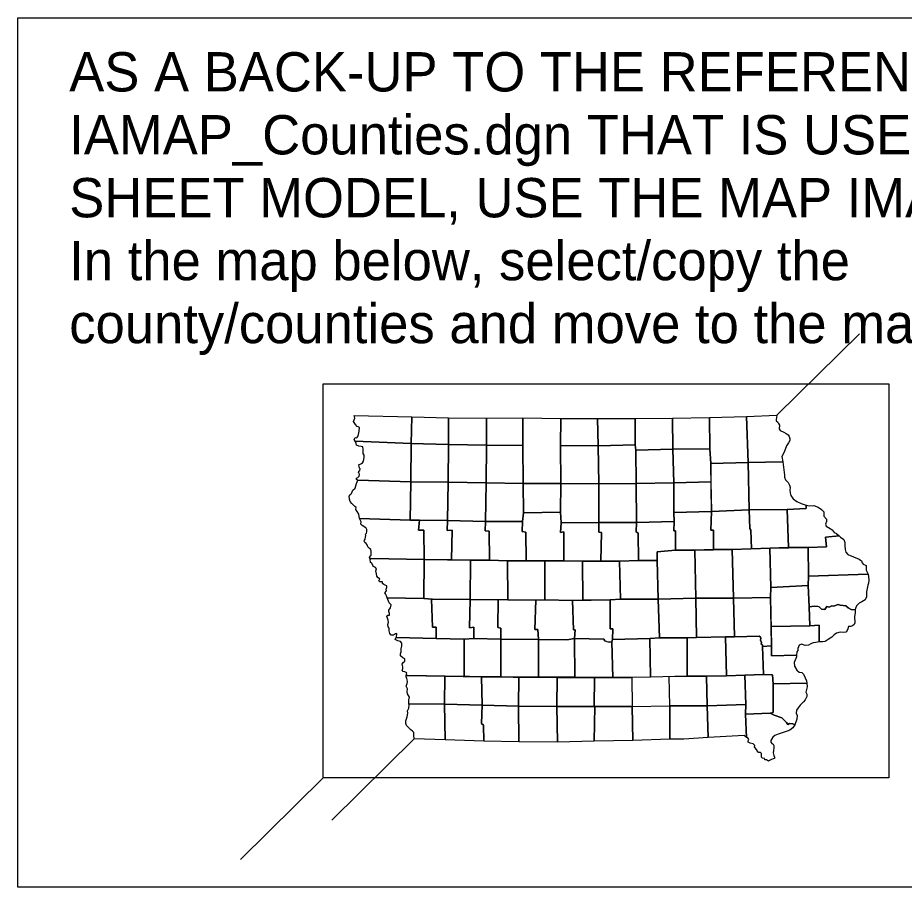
# Model space of a CAD drawing. Extents: x -0.84 to 4.97, y -1.01 to 2.42.
# Drawn here: x -0.1003 to 0.3692, y -0.6865 to -0.2258 of the extents above; entities that cross this region are included whole.
import ezdxf

# ---------------------------------------------------------------- set-up
doc = ezdxf.new("R2010")
doc.units = 0
doc.layers.add('tdCoTitleBlock', color=7, linetype='Continuous')
doc.layers.add('TextNonPlot', color=7, linetype='Continuous')

msp = doc.modelspace()

# ---------------------------------------------------------------- linework, layer by layer
at = {"layer": 'tdCoTitleBlock'}
for points in [[(0.07788, -0.43657), (0.10843, -0.43731), (0.10809, -0.45142), (0.07838, -0.45021), (0.07776, -0.44923), (0.07832, -0.44824), (0.07927, -0.44843), (0.07977, -0.44775), (0.08007, -0.44667), (0.08041, -0.44485), (0.08062, -0.44282), (0.07997, -0.44257), (0.07935, -0.44233), (0.07858, -0.44134), (0.07755, -0.43971), (0.0782, -0.43799)], [(0.28556, -0.43711), (0.30171, -0.43644), (0.30149, -0.4377), (0.30131, -0.43851), (0.30138, -0.43931), (0.30218, -0.44014), (0.30265, -0.44075), (0.30302, -0.44167), (0.3029, -0.44368), (0.30346, -0.44457), (0.30535, -0.44536), (0.30658, -0.44613), (0.3077, -0.44683), (0.30829, -0.44772), (0.30857, -0.44883), (0.30851, -0.44982), (0.30786, -0.45099), (0.30682, -0.45263), (0.30562, -0.45599), (0.3043, -0.45824), (0.30493, -0.46116), (0.28658, -0.46137)], [(0.10843, -0.43731), (0.12788, -0.43771), (0.12783, -0.452), (0.10809, -0.45142)], [(0.12788, -0.43771), (0.14789, -0.43796), (0.14784, -0.45219), (0.12783, -0.452)], [(0.14789, -0.43796), (0.16716, -0.43778), (0.16711, -0.45238), (0.14784, -0.45219)], [(0.16716, -0.43778), (0.1873, -0.43821), (0.18715, -0.45253), (0.18736, -0.47252), (0.16738, -0.47252), (0.16711, -0.45238)], [(0.1873, -0.43821), (0.20669, -0.43821), (0.20704, -0.45262), (0.18715, -0.45253)], [(0.20669, -0.43821), (0.2267, -0.43809), (0.22671, -0.45204), (0.20704, -0.45262)], [(0.2267, -0.43809), (0.24643, -0.4379), (0.24664, -0.45438), (0.227, -0.455), (0.22671, -0.45204)], [(0.24643, -0.4379), (0.26604, -0.4376), (0.26627, -0.4542), (0.24664, -0.45438)], [(0.26604, -0.4376), (0.28556, -0.43711), (0.28658, -0.46137), (0.2667, -0.46196), (0.26627, -0.4542)], [(0.07838, -0.45021), (0.10809, -0.45142), (0.10787, -0.47168), (0.07977, -0.47085), (0.07915, -0.47054), (0.07903, -0.46983), (0.07983, -0.46943), (0.08041, -0.46866), (0.08063, -0.46783), (0.08056, -0.46712), (0.08022, -0.46672), (0.08031, -0.46607), (0.08087, -0.46561), (0.08108, -0.46487), (0.08068, -0.46438), (0.08043, -0.46348), (0.08033, -0.46259), (0.08107, -0.4624), (0.08169, -0.462), (0.08221, -0.4616), (0.08274, -0.46083), (0.08292, -0.45978), (0.08319, -0.45855), (0.08319, -0.45759), (0.08266, -0.45661), (0.08254, -0.45531), (0.08269, -0.45448), (0.08241, -0.45322), (0.08157, -0.45298), (0.08027, -0.45277), (0.07916, -0.45225), (0.07891, -0.45145)], [(0.10809, -0.45142), (0.12783, -0.452), (0.12758, -0.47193), (0.10787, -0.47168)], [(0.12783, -0.452), (0.14784, -0.45219), (0.14777, -0.47215), (0.12758, -0.47193)], [(0.14784, -0.45219), (0.16711, -0.45238), (0.16738, -0.47252), (0.14777, -0.47215)], [(0.18715, -0.45253), (0.20704, -0.45262), (0.2075, -0.47267), (0.18736, -0.47252)], [(0.20704, -0.45262), (0.22671, -0.45204), (0.227, -0.455), (0.22723, -0.47258), (0.2075, -0.47267)], [(0.227, -0.455), (0.24664, -0.45438), (0.24706, -0.47218), (0.22723, -0.47258)], [(0.24664, -0.45438), (0.26627, -0.4542), (0.2667, -0.46196), (0.26682, -0.47175), (0.24706, -0.47218)], [(0.2667, -0.46196), (0.28658, -0.46137), (0.28712, -0.4866), (0.26714, -0.48743)], [(0.28658, -0.46137), (0.30493, -0.46116), (0.30553, -0.4668), (0.30581, -0.46815), (0.30572, -0.46929), (0.30631, -0.47055), (0.30764, -0.472), (0.30842, -0.47344), (0.3087, -0.47477), (0.30861, -0.47609), (0.30874, -0.47757), (0.30911, -0.47898), (0.31032, -0.48064), (0.31227, -0.48212), (0.31465, -0.48316), (0.31725, -0.48413), (0.31726, -0.48574), (0.30713, -0.48638), (0.28712, -0.4866)], [(0.07977, -0.47085), (0.10787, -0.47168), (0.10753, -0.49192), (0.08072, -0.49117), (0.08035, -0.48889), (0.07942, -0.48733), (0.0787, -0.4864), (0.07898, -0.4852), (0.0782, -0.48477), (0.07662, -0.48321), (0.07576, -0.48207), (0.07538, -0.48081), (0.07516, -0.4793), (0.07572, -0.4785), (0.07645, -0.47779), (0.07707, -0.47606), (0.07836, -0.47513), (0.07906, -0.47254)], [(0.10787, -0.47168), (0.12758, -0.47193), (0.12729, -0.4922), (0.11244, -0.49194), (0.10753, -0.49192)], [(0.12758, -0.47193), (0.14777, -0.47215), (0.14746, -0.49279), (0.12729, -0.4922)], [(0.14777, -0.47215), (0.16738, -0.47252), (0.16755, -0.48807), (0.16707, -0.49269), (0.14746, -0.49279)], [(0.16738, -0.47252), (0.18736, -0.47252), (0.18707, -0.48771), (0.16755, -0.48807)], [(0.18736, -0.47252), (0.2075, -0.47267), (0.20737, -0.49331), (0.18739, -0.49334), (0.18707, -0.48771)], [(0.2075, -0.47267), (0.22723, -0.47258), (0.22741, -0.49322), (0.20743, -0.49325)], [(0.22723, -0.47258), (0.24706, -0.47218), (0.24719, -0.48798), (0.24727, -0.4927), (0.22741, -0.49322)], [(0.24706, -0.47218), (0.26682, -0.47175), (0.26714, -0.48743), (0.24719, -0.48798)], [(0.16755, -0.48807), (0.18707, -0.48771), (0.18739, -0.49334), (0.18704, -0.49849), (0.18895, -0.49823), (0.18881, -0.51357), (0.1789, -0.5136), (0.16889, -0.51339), (0.16869, -0.49829), (0.16681, -0.49799), (0.16707, -0.49269)], [(0.24719, -0.48798), (0.26714, -0.48743), (0.2668, -0.49732), (0.26819, -0.49737), (0.26822, -0.50754), (0.25831, -0.50797), (0.24799, -0.50797), (0.24796, -0.49771), (0.24716, -0.49769), (0.24727, -0.4927)], [(0.26714, -0.48743), (0.28712, -0.4866), (0.28739, -0.49639), (0.28798, -0.49722), (0.2882, -0.50717), (0.27801, -0.50748), (0.26822, -0.50754), (0.26819, -0.49737), (0.2668, -0.49732)], [(0.28712, -0.4866), (0.30713, -0.48638), (0.3078, -0.50655), (0.2882, -0.50717), (0.28798, -0.49722), (0.28739, -0.49639)], [(0.30713, -0.48638), (0.31726, -0.48574), (0.31725, -0.48413), (0.31892, -0.48438), (0.32127, -0.48431), (0.32365, -0.48507), (0.32526, -0.48636), (0.32653, -0.48765), (0.3265, -0.48987), (0.32808, -0.49155), (0.32796, -0.49276), (0.32747, -0.49411), (0.32775, -0.49525), (0.33001, -0.49642), (0.331, -0.49715), (0.33205, -0.4985), (0.33326, -0.49912), (0.33462, -0.50028), (0.32746, -0.50095), (0.32794, -0.50619), (0.31824, -0.5064), (0.3078, -0.50655)], [(0.08072, -0.49117), (0.10753, -0.49192), (0.11244, -0.49194), (0.11184, -0.49733), (0.1148, -0.49729), (0.11485, -0.51275), (0.0868, -0.51234), (0.08628, -0.51272), (0.08591, -0.51173), (0.08655, -0.51093), (0.08686, -0.51053), (0.0868, -0.50979), (0.08676, -0.50889), (0.08692, -0.50837), (0.0867, -0.50748), (0.08589, -0.50693), (0.08506, -0.50616), (0.08475, -0.50499), (0.08416, -0.50434), (0.08348, -0.50388), (0.08307, -0.50315), (0.08329, -0.50256), (0.08359, -0.50207), (0.08378, -0.50108), (0.08396, -0.50016), (0.0839, -0.49945), (0.08433, -0.49883), (0.08451, -0.49818), (0.08451, -0.49695), (0.08426, -0.49615), (0.0837, -0.49584), (0.0829, -0.49539), (0.08215, -0.49477), (0.08135, -0.49403), (0.08153, -0.4928)], [(0.11244, -0.49194), (0.12729, -0.4922), (0.12709, -0.49744), (0.12981, -0.49737), (0.12939, -0.51301), (0.11485, -0.51275), (0.1148, -0.49729), (0.11184, -0.49733)], [(0.12729, -0.4922), (0.14746, -0.49279), (0.14717, -0.49765), (0.14939, -0.49777), (0.1495, -0.51314), (0.13946, -0.51323), (0.12939, -0.51301), (0.12981, -0.49737), (0.12709, -0.49744)], [(0.14746, -0.49279), (0.16707, -0.49269), (0.16681, -0.49799), (0.16869, -0.49829), (0.16889, -0.51339), (0.15901, -0.51363), (0.1495, -0.51314), (0.14939, -0.49777), (0.14717, -0.49765)], [(0.22741, -0.49322), (0.24727, -0.4927), (0.24716, -0.49769), (0.24796, -0.49771), (0.24799, -0.50797), (0.23839, -0.50871), (0.23834, -0.51342), (0.22837, -0.51342), (0.22823, -0.49894), (0.22727, -0.49824)], [(0.18739, -0.49334), (0.20743, -0.49325), (0.20739, -0.49836), (0.20884, -0.49854), (0.20854, -0.51367), (0.19869, -0.51379), (0.18881, -0.51357), (0.18895, -0.49823), (0.18704, -0.49849)], [(0.20743, -0.49325), (0.22741, -0.49322), (0.22727, -0.49824), (0.22823, -0.49894), (0.22837, -0.51342), (0.21842, -0.51367), (0.20854, -0.51367), (0.20884, -0.49854), (0.20739, -0.49836)], [(0.31824, -0.5064), (0.32794, -0.50619), (0.32746, -0.50095), (0.33462, -0.50028), (0.33546, -0.50102), (0.33725, -0.50228), (0.33772, -0.50378), (0.33769, -0.50557), (0.33791, -0.50748), (0.33832, -0.50902), (0.33934, -0.51025), (0.34531, -0.51263), (0.34645, -0.51349), (0.34683, -0.51463), (0.34739, -0.51534), (0.34896, -0.51601), (0.34903, -0.51856), (0.35006, -0.52062), (0.3185, -0.52171)], [(0.27801, -0.50748), (0.29805, -0.50689), (0.29857, -0.52765), (0.29837, -0.53295), (0.27876, -0.53338)], [(0.29805, -0.50689), (0.31824, -0.5064), (0.3185, -0.52171), (0.31836, -0.52664), (0.29857, -0.52765)], [(0.23839, -0.50871), (0.24799, -0.50797), (0.25831, -0.50797), (0.25884, -0.53335), (0.23877, -0.53378), (0.23834, -0.51342)], [(0.25831, -0.50797), (0.27801, -0.50748), (0.27876, -0.53338), (0.25884, -0.53335)], [(0.08628, -0.51272), (0.0868, -0.51234), (0.11485, -0.51275), (0.11466, -0.53357), (0.09536, -0.53314), (0.09492, -0.53209), (0.09452, -0.53108), (0.09402, -0.53046), (0.09488, -0.52941), (0.09476, -0.52864), (0.09506, -0.52769), (0.09506, -0.52679), (0.09432, -0.52637), (0.09432, -0.52637), (0.09348, -0.52609), (0.09293, -0.52548), (0.09289, -0.52471), (0.09206, -0.52465), (0.09144, -0.52465), (0.09098, -0.5241), (0.09144, -0.52311), (0.09063, -0.52247), (0.08989, -0.5217), (0.08964, -0.52047), (0.08939, -0.51884), (0.08966, -0.51782), (0.08966, -0.51782), (0.0892, -0.51705), (0.08811, -0.51662), (0.08768, -0.51607), (0.08727, -0.51481), (0.08653, -0.51438)], [(0.11485, -0.51275), (0.13946, -0.51323), (0.1393, -0.53405), (0.11935, -0.53377), (0.11466, -0.53357)], [(0.13946, -0.51323), (0.1495, -0.51314), (0.15901, -0.51363), (0.15916, -0.53418), (0.1393, -0.53405)], [(0.15901, -0.51363), (0.1789, -0.5136), (0.17886, -0.53427), (0.17404, -0.53441), (0.15916, -0.53418)], [(0.1789, -0.5136), (0.19869, -0.51379), (0.199, -0.53442), (0.19353, -0.53447), (0.17886, -0.53427)], [(0.19869, -0.51379), (0.21842, -0.51367), (0.21894, -0.53381), (0.21345, -0.53426), (0.199, -0.53442)], [(0.21842, -0.51367), (0.22837, -0.51342), (0.23834, -0.51342), (0.23877, -0.53378), (0.21894, -0.53381)], [(0.3185, -0.52171), (0.35006, -0.52062), (0.35025, -0.52179), (0.35037, -0.52373), (0.35026, -0.52531), (0.34995, -0.52635), (0.34952, -0.5282), (0.34919, -0.52999), (0.3491, -0.53264), (0.34846, -0.53424), (0.34673, -0.53526), (0.34538, -0.53601), (0.34393, -0.53743), (0.34338, -0.53879), (0.34322, -0.53946), (0.341, -0.53932), (0.33952, -0.53852), (0.33822, -0.53732), (0.33676, -0.53724), (0.33519, -0.53709), (0.3342, -0.53675), (0.33173, -0.5375), (0.33077, -0.53735), (0.32942, -0.53815), (0.32892, -0.53788), (0.32812, -0.53766), (0.3272, -0.53936), (0.32531, -0.53918), (0.3242, -0.53789), (0.32169, -0.53753), (0.31876, -0.53785), (0.31836, -0.52664)], [(0.29857, -0.52765), (0.31836, -0.52664), (0.31876, -0.53785), (0.31913, -0.54789), (0.29863, -0.54829), (0.29837, -0.53295)], [(0.09536, -0.53314), (0.11466, -0.53357), (0.11878, -0.53377), (0.11924, -0.54865), (0.12134, -0.54877), (0.12131, -0.55469), (0.10019, -0.55413), (0.10035, -0.55204), (0.09967, -0.55219), (0.09875, -0.5529), (0.09742, -0.55288), (0.09677, -0.55205), (0.09639, -0.55069), (0.09645, -0.54921), (0.09589, -0.54845), (0.09574, -0.54731), (0.09601, -0.5461), (0.09579, -0.54496), (0.09548, -0.54392), (0.09511, -0.543), (0.09563, -0.54238), (0.09656, -0.54238), (0.09652, -0.54139), (0.09618, -0.54047), (0.09621, -0.53973), (0.09716, -0.53852), (0.0974, -0.53692), (0.09644, -0.53582)], [(0.11878, -0.53377), (0.1393, -0.53405), (0.13894, -0.54902), (0.14117, -0.54871), (0.14127, -0.55471), (0.13603, -0.55504), (0.12131, -0.55469), (0.12134, -0.54877), (0.11924, -0.54865)], [(0.1393, -0.53405), (0.15416, -0.53404), (0.15386, -0.54882), (0.15543, -0.54919), (0.15551, -0.55498), (0.14127, -0.55471), (0.14117, -0.54871), (0.13894, -0.54902)], [(0.15416, -0.53404), (0.15916, -0.53418), (0.17404, -0.53441), (0.17353, -0.5499), (0.17514, -0.54999), (0.17549, -0.55525), (0.15551, -0.55498), (0.15543, -0.54919), (0.15386, -0.54882)], [(0.17404, -0.53441), (0.17886, -0.53427), (0.19353, -0.53447), (0.19404, -0.55002), (0.19496, -0.55014), (0.19461, -0.55477), (0.19041, -0.55539), (0.17549, -0.55525), (0.17514, -0.54999), (0.17353, -0.5499)], [(0.19404, -0.55002), (0.19353, -0.53447), (0.21345, -0.53426), (0.21337, -0.5495), (0.21476, -0.54965), (0.21468, -0.55523), (0.21431, -0.55652), (0.21295, -0.55668), (0.21178, -0.5565), (0.21064, -0.55586), (0.21002, -0.55512), (0.19461, -0.55477), (0.19496, -0.55014)], [(0.21345, -0.53426), (0.21894, -0.53381), (0.23877, -0.53378), (0.23957, -0.55438), (0.23444, -0.55474), (0.21468, -0.55523), (0.21476, -0.54965), (0.21337, -0.5495)], [(0.23877, -0.53378), (0.25884, -0.53335), (0.25918, -0.5542), (0.23957, -0.55438)], [(0.25884, -0.53335), (0.27876, -0.53338), (0.27931, -0.55389), (0.27459, -0.55378), (0.25918, -0.5542)], [(0.27876, -0.53338), (0.29837, -0.53295), (0.2989, -0.55851), (0.29405, -0.5589), (0.29408, -0.55806), (0.2934, -0.5577), (0.29352, -0.55683), (0.29303, -0.55557), (0.29327, -0.55449), (0.29299, -0.554), (0.29228, -0.55348), (0.27931, -0.55389)], [(0.31876, -0.53785), (0.32169, -0.53753), (0.3233, -0.53762), (0.3242, -0.53789), (0.32531, -0.53918), (0.3272, -0.53936), (0.32812, -0.53766), (0.32892, -0.53788), (0.32942, -0.53815), (0.33077, -0.53735), (0.33173, -0.5375), (0.3342, -0.53675), (0.33519, -0.53709), (0.33676, -0.53724), (0.33822, -0.53732), (0.33952, -0.53852), (0.341, -0.53932), (0.34322, -0.53946), (0.34311, -0.54113), (0.34283, -0.5431), (0.34297, -0.54633), (0.34272, -0.54735), (0.34173, -0.54797), (0.34093, -0.54828), (0.34022, -0.54828), (0.33973, -0.54841), (0.33933, -0.54952), (0.33902, -0.55044), (0.33822, -0.55125), (0.33693, -0.55143), (0.33532, -0.55132), (0.33322, -0.55194), (0.33199, -0.55277), (0.33079, -0.55404), (0.32891, -0.55522), (0.32728, -0.55627), (0.32579, -0.55652), (0.32419, -0.55646), (0.32419, -0.54762), (0.31913, -0.54789)], [(0.29863, -0.54829), (0.31913, -0.54789), (0.32419, -0.54762), (0.32419, -0.55646), (0.32243, -0.55681), (0.32098, -0.55706), (0.31974, -0.55752), (0.31848, -0.55814), (0.31678, -0.5584), (0.31474, -0.55769), (0.3136, -0.55816), (0.31289, -0.55998), (0.31287, -0.56103), (0.31228, -0.56177), (0.31219, -0.56349), (0.29892, -0.5639), (0.2989, -0.55851)], [(0.25417, -0.55434), (0.25918, -0.5542), (0.27459, -0.55378), (0.27498, -0.57439), (0.26452, -0.57463), (0.25429, -0.57463)], [(0.27459, -0.55378), (0.27931, -0.55389), (0.29228, -0.55348), (0.29299, -0.554), (0.29327, -0.55449), (0.29303, -0.55557), (0.29334, -0.55625), (0.29352, -0.55683), (0.2934, -0.5577), (0.29408, -0.55806), (0.29405, -0.5589), (0.29459, -0.5738), (0.28483, -0.57405), (0.27498, -0.57439)], [(0.10019, -0.55413), (0.12131, -0.55469), (0.13603, -0.55504), (0.13611, -0.57478), (0.10603, -0.57422), (0.10535, -0.57429), (0.10581, -0.57287), (0.10464, -0.57238), (0.10371, -0.57217), (0.10331, -0.57149), (0.10365, -0.57069), (0.10361, -0.56961), (0.1033, -0.56823), (0.10373, -0.56739), (0.10475, -0.56671), (0.10474, -0.56554), (0.1036, -0.56487), (0.10236, -0.56395), (0.10233, -0.56278), (0.10275, -0.56167), (0.10275, -0.5601), (0.10309, -0.55862), (0.10314, -0.55711), (0.10246, -0.55622), (0.10098, -0.55594), (0.09953, -0.55518), (0.09989, -0.55432)], [(0.13603, -0.55504), (0.14127, -0.55471), (0.15551, -0.55498), (0.15553, -0.57506), (0.14939, -0.57495), (0.13898, -0.57486), (0.13611, -0.57478)], [(0.15551, -0.55498), (0.17549, -0.55525), (0.17539, -0.57518), (0.16208, -0.57516), (0.15553, -0.57506)], [(0.17549, -0.55525), (0.19041, -0.55539), (0.19461, -0.55477), (0.19473, -0.57519), (0.17539, -0.57518)], [(0.19461, -0.55477), (0.21002, -0.55512), (0.21064, -0.55586), (0.21295, -0.55668), (0.21431, -0.55652), (0.21489, -0.57534), (0.19473, -0.57519)], [(0.21468, -0.55523), (0.23444, -0.55474), (0.23472, -0.57512), (0.21489, -0.57534), (0.21431, -0.55652)], [(0.23444, -0.55474), (0.23957, -0.55438), (0.25417, -0.55434), (0.25429, -0.57463), (0.23472, -0.57512)], [(0.29405, -0.5589), (0.2989, -0.55851), (0.29892, -0.5639), (0.31219, -0.56349), (0.3121, -0.56435), (0.31094, -0.56738), (0.3111, -0.56932), (0.31234, -0.57147), (0.31349, -0.57254), (0.31485, -0.57278), (0.31574, -0.57364), (0.31671, -0.57558), (0.31671, -0.57558), (0.31739, -0.57715), (0.31761, -0.57832), (0.29979, -0.57878), (0.29947, -0.57388), (0.29459, -0.5738)], [(0.10535, -0.57429), (0.10603, -0.57422), (0.1258, -0.57456), (0.12569, -0.58956), (0.10679, -0.58938), (0.10675, -0.58854), (0.10678, -0.58731), (0.10712, -0.58577), (0.10603, -0.58399), (0.10596, -0.58276), (0.10611, -0.58134), (0.10577, -0.58057), (0.10546, -0.57992), (0.10586, -0.5786), (0.1061, -0.57764), (0.10595, -0.57666), (0.10567, -0.5758), (0.10532, -0.57494)], [(0.1258, -0.57456), (0.1452, -0.57491), (0.1457, -0.59006), (0.12569, -0.58956)], [(0.1452, -0.57491), (0.14939, -0.57495), (0.15553, -0.57506), (0.16208, -0.57516), (0.16503, -0.57517), (0.16494, -0.59052), (0.1457, -0.59006)], [(0.16503, -0.57517), (0.18534, -0.57528), (0.1852, -0.59074), (0.16494, -0.59052)], [(0.18534, -0.57528), (0.20504, -0.57543), (0.20499, -0.59077), (0.1852, -0.59074)], [(0.20504, -0.57543), (0.22493, -0.57531), (0.22506, -0.59065), (0.20499, -0.59077)], [(0.24472, -0.57488), (0.25429, -0.57463), (0.26452, -0.57463), (0.26471, -0.59034), (0.24501, -0.59034)], [(0.26452, -0.57463), (0.27498, -0.57439), (0.28483, -0.57405), (0.28522, -0.58966), (0.26471, -0.59034)], [(0.28483, -0.57405), (0.29459, -0.5738), (0.29947, -0.57388), (0.29979, -0.57878), (0.2998, -0.59393), (0.29808, -0.5943), (0.28514, -0.59484), (0.28522, -0.58966)], [(0.29979, -0.57878), (0.31761, -0.57832), (0.31771, -0.58023), (0.31747, -0.58177), (0.31704, -0.58316), (0.31766, -0.58417), (0.31766, -0.5855), (0.31668, -0.58726), (0.31575, -0.58818), (0.31406, -0.59007), (0.31298, -0.59139), (0.31215, -0.59269), (0.31185, -0.5942), (0.31241, -0.59555), (0.31223, -0.5974), (0.31125, -0.60039), (0.31011, -0.59997), (0.30847, -0.59969), (0.3076, -0.60028), (0.30686, -0.59911), (0.30429, -0.59678), (0.30021, -0.59538), (0.29808, -0.5943), (0.2998, -0.59393)], [(0.10679, -0.58938), (0.12569, -0.58956), (0.12595, -0.60838), (0.10968, -0.60782), (0.1094, -0.60597), (0.10939, -0.60443), (0.10877, -0.60378), (0.10784, -0.60311), (0.10679, -0.602), (0.10555, -0.60084), (0.10524, -0.59976), (0.10527, -0.59831), (0.10585, -0.59622), (0.10618, -0.59424), (0.10609, -0.59304), (0.10679, -0.59156), (0.10697, -0.58987)], [(0.12569, -0.58956), (0.1457, -0.59006), (0.14529, -0.59973), (0.14638, -0.60053), (0.14652, -0.60915), (0.12595, -0.60838)], [(0.1457, -0.59006), (0.16494, -0.59052), (0.16505, -0.60943), (0.14652, -0.60915), (0.14638, -0.60053), (0.14529, -0.59973)], [(0.16494, -0.59052), (0.1852, -0.59074), (0.18559, -0.60962), (0.16505, -0.60943)], [(0.1852, -0.59074), (0.20533, -0.59065), (0.20501, -0.60916), (0.18559, -0.60962)], [(0.20533, -0.59065), (0.22506, -0.59065), (0.22539, -0.60873), (0.20501, -0.60916)], [(0.22506, -0.59065), (0.24501, -0.59034), (0.24509, -0.60802), (0.22539, -0.60873)], [(0.24501, -0.59034), (0.26471, -0.59034), (0.26537, -0.60721), (0.25247, -0.60793), (0.24509, -0.60802)], [(0.26471, -0.59034), (0.28522, -0.58966), (0.28514, -0.59484), (0.28554, -0.60706), (0.28446, -0.60602), (0.26537, -0.60721)], [(0.28514, -0.59484), (0.29808, -0.5943), (0.30021, -0.59538), (0.30429, -0.59678), (0.30686, -0.59911), (0.3076, -0.60028), (0.30847, -0.59969), (0.31011, -0.59997), (0.31125, -0.60039), (0.3102, -0.60209), (0.30863, -0.60323), (0.30721, -0.60373), (0.3045, -0.60466), (0.30246, -0.60544), (0.3007, -0.60612), (0.29966, -0.60696), (0.29849, -0.60866), (0.29855, -0.60964), (0.29905, -0.61029), (0.29967, -0.61075), (0.30016, -0.61139), (0.30017, -0.61256), (0.29986, -0.61404), (0.29974, -0.61534), (0.30009, -0.61666), (0.30052, -0.61758), (0.3004, -0.61826), (0.29981, -0.61851), (0.29879, -0.61873), (0.29781, -0.61931), (0.29731, -0.61975), (0.29614, -0.61889), (0.29534, -0.61889), (0.29524, -0.61821), (0.29413, -0.61803), (0.29354, -0.6176), (0.29363, -0.61652), (0.29354, -0.6156), (0.29298, -0.61505), (0.29193, -0.61505), (0.2914, -0.61431), (0.29094, -0.61345), (0.29013, -0.61269), (0.28991, -0.61201), (0.29, -0.61142), (0.2891, -0.6105), (0.28765, -0.6102), (0.28657, -0.60965), (0.28657, -0.60894), (0.28694, -0.60811), (0.28632, -0.60737), (0.28554, -0.60706)]]:
    msp.add_lwpolyline(points, close=True, dxfattribs=at)
at = {"layer": 'TextNonPlot'}
for p, q in [((0.34544, -0.39328), (0.30171, -0.43644)), ((0.10968, -0.60782), (0.06594, -0.65098)), ((0.06146, -0.62855), (0.01772, -0.67172))]:
    msp.add_line(p, q, dxfattribs=at)
for points in [[(-0.10034, -0.22582), (0.74797, -0.22582), (0.74797, -0.68648), (-0.10034, -0.68648)], [(0.06146, -0.4197), (0.36095, -0.4197), (0.36095, -0.62855), (0.06146, -0.62855)]]:
    msp.add_lwpolyline(points, close=True, dxfattribs=at)

# ---------------------------------------------------------------- texts
for s, p in [('AS A BACK-UP TO THE REFERENCED ', (-0.07307, -0.2649)), ('IAMAP_Counties.dgn THAT IS USED ON THE TITLE ', (-0.07307, -0.29824)), ('SHEET MODEL, USE THE MAP IMAGE BELOW.', (-0.07307, -0.33157)), ('In the map below, select/copy the ', (-0.07307, -0.3649)), ('county/counties and move to the map above.', (-0.07307, -0.39824))]:
    msp.add_text(s, height=0.0208333, dxfattribs=at).set_placement(p)

doc.saveas('drawing.dxf')
